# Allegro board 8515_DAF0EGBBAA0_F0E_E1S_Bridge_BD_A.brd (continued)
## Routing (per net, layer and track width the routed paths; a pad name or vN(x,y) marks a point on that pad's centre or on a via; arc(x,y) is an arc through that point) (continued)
P3E_E1S_2_RX_DN2: length 45.1
  TOP w0.132: v3(81.03,30.78) 81.4,30.4 81.68,30.4 82.45,31.17 82.89,31.17 83.02,31.3 J6.A23
  BOTTOM w0.132: GF1.A50 56.97,3.16 57.1,3.29 57.1,6.03 62.01,13.03 65.28,15.32 72.13,16.53 74.32,18.72 v4(75.42,24.94) 75.78,26.99 77.13,28.93 77.79,29.39 78.79,29.39 80.3,30.45 80.7,30.45 v3(81.03,30.78)
P3E_E1S_2_RX_DN3: length 45.4
  TOP w0.132: J6.A26 84.6,29.49 84.73,29.37 85.28,29.37 v3(85.62,29.7)
  BOTTOM w0.132: GF1.A53 58.77,3.16 58.84,3.23 58.84,5.76 58.92,6.18 62.9,11.86 66.28,14.23 69.39,14.78 v4(70.02,14.89) 70.44,14.97 72.7,15.37 74.5,16.6 75.46,17.56 75.65,17.83 75.86,18.13 76.57,19.32 76.63,19.71 77.15,22.63 77.16,22.64 77.78,26.11 78.41,27.02 80.03,28.15 81.25,28.15 82.78,29.22 83.96,29.43 84.33,29.37 85.28,29.37 v3(85.62,29.7)
P3E_E1S_2_RX_DP0: length 50.1
  TOP w0.132: v3(81.54,34.09) 81.87,34.42 82.89,34.42 83.02,34.3 J6.A18
  BOTTOM w0.132: GF1.A45 53.97,3.16 53.84,3.29 53.84,6.02 59.53,14.15 64.57,17.67 v4(65.33,17.8) 70.47,18.71 70.92,19.02 72.2,26.3 73.41,28.03 73.7,28.08 73.92,28.4 73.87,28.69 74.1,29.01 74.38,29.06 74.61,29.38 74.56,29.67 74.79,29.99 75.07,30.04 75.3,30.37 75.25,30.65 75.47,30.97 77.85,32.64 78.62,32.64 79.48,33.24 79.91,33.86 80.72,34.42 81.25,34.42 81.54,34.14 v3(81.54,34.09)
P3E_E1S_2_RX_DP1: length 51.1
  TOP w0.132: J6.A21 84.6,32.49 84.73,32.62 85.33,32.62 v3(85.67,32.29)
  BOTTOM w0.132: GF1.A48 55.77,3.16 55.64,3.29 55.64,5.94 60.81,13.32 65.13,16.35 71.21,17.42 72.45,18.28 73.17,22.35 73.41,22.52 73.48,22.91 73.31,23.15 73.38,23.54 73.62,23.71 73.69,24.1 73.52,24.34 73.59,24.73 73.83,24.89 73.9,25.28 73.73,25.52 73.8,25.91 74.78,27.31 74.86,27.42 76.73,30.1 v4(77.02,30.31) 77.36,30.54 77.72,30.8 78.63,30.8 80.66,32.22 81.04,32.28 81.81,32.28 82.39,32.54 83.44,32.77 84.23,32.61 85.46,32.61 85.67,32.39 v3(85.67,32.29)
P3E_E1S_2_RX_DP2: length 45.1
  TOP w0.132: v3(81.03,29.76) 81.33,30.06 81.83,30.06 82.59,30.82 82.89,30.82 83.02,30.7 J6.A24
  BOTTOM w0.132: GF1.A51 57.57,3.16 57.44,3.29 57.44,5.92 62.25,12.79 65.42,15 72.3,16.22 74.64,18.56 74.79,19.44 74.8,19.44 75,20.62 75.24,20.79 75.31,21.17 75.14,21.41 v4(75.22,21.87) 75.22,21.87 75.23,21.91 75.45,23.17 75.45,23.17 75.69,24.49 75.92,24.66 75.99,25.05 75.83,25.29 75.89,25.67 76.13,25.84 76.2,26.23 76.03,26.47 76.1,26.85 76.52,27.46 76.53,27.46 77.38,28.69 77.9,29.05 78.9,29.05 80.41,30.11 80.73,30.11 81.03,29.82 v3(81.03,29.76)
P3E_E1S_2_RX_DP3: length 45.4
  TOP w0.132: v3(85.62,28.69) 85.28,29.02 84.73,29.02 84.6,28.9 J6.A27
  BOTTOM w0.132: v3(85.62,28.69) 85.28,29.02 84.3,29.02 83.96,29.09 82.92,28.9 81.45,27.87 81.39,27.81 80.14,27.81 78.65,26.78 78.1,25.98 78.03,25.59 78.2,25.36 78.13,24.97 77.89,24.8 77.82,24.41 77.99,24.17 77.92,23.79 77.68,23.62 77.61,23.23 77.78,22.99 77.71,22.61 77.46,22.43 76.97,19.68 76.89,19.2 76.15,17.95 75.93,17.63 75.72,17.34 74.72,16.33 v4(74.01,15.85) 73.61,15.58 72.83,15.04 66.42,13.91 63.14,11.62 59.24,6.05 59.18,5.73 59.18,3.35 59.37,3.16 GF1.A54
P3E_E1S_2_TX_DN0: length 46.7
  TOP w0.132: GF1.B44 53.37,3.16 53.5,3.29 53.5,6.48 59.76,15.42 60.01,15.78 v4(60.34,16.25) 60.55,16.54 60.73,16.8 64.15,17.41 65.7,17.68 67.15,17.94 70.5,18.53 71.84,22.3 72.06,22.9 72.16,23.19 72.27,23.5 72.59,25.32 73.41,29.97 74.61,31.68 74.85,31.93 74.94,32.06 77.31,34.42 77.48,34.54 77.69,34.69 77.72,34.7 78.33,34.8 78.42,34.9 J6.B17
P3E_E1S_2_TX_DN1: length 45.5
  TOP w0.132: J6.B20 78.42,33.09 78.34,33.02 78.03,33.02 77.87,32.98 77.72,32.89 77.41,32.72 76.81,32.15 75.55,30.89 74.64,29.58 v4(74.64,28.54) 74.64,27.1 74.58,26.92 74.58,26.92 74.44,26.46 74.67,26.05 75.06,25.93 75.16,25.75 75.02,25.28 74.86,25.19 74.45,25.31 74.04,25.09 72.25,19.12 72.06,18.06 71.29,17.29 61.81,15.62 60.94,14.38 60.3,13.46 59.92,12.93 59.68,12.59 55.3,6.33 55.3,3.29 55.17,3.16 GF1.B47
P3E_E1S_2_TX_DN2: length 42.3
  TOP w0.132: GF1.B50 56.97,3.16 57.1,3.29 57.1,6.36 57.16,6.42 62.2,13.61 62.85,14.26 63.34,14.35 70.82,15.66 71.42,15.77 72.53,16.55 72.53,16.55 73.3,17.08 73.75,19.66 v4(74.43,21.89) 74.49,22.1 74.85,23.29 76.39,24.88 76.46,26.22 75.86,27.62 75.86,28.33 76.03,29.27 76.8,30.36 77.72,31.01 77.99,31.2 78.41,31.2 78.51,31.3 J6.B23
P3E_E1S_2_TX_DN3: length 41
  TOP w0.132: J6.B26 78.51,29.49 78.41,29.39 78.13,29.39 77.8,29.13 77.72,29.07 77.33,28.74 77.18,27.9 77.8,26.44 77.56,23.94 75.93,22.62 75.77,22.09 75.99,21.67 76.29,21.58 76.38,21.42 76.23,20.94 76.07,20.85 75.77,20.94 75.36,20.72 75.08,19.81 v4(74.95,19.13) 74.88,18.79 74.52,16.95 74.25,15.43 73.43,14.6 67,13.47 63.97,12.94 63.53,12.66 63.19,12.45 62.43,11.36 62.23,11.07 61.88,10.57 58.9,6.32 58.9,3.29 58.77,3.16 GF1.B53
P3E_E1S_2_TX_DP0: length 46.8
  TOP w0.132: J6.B18 78.5,34.3 78.33,34.46 77.83,34.37 77.72,34.3 77.53,34.16 75.21,31.84 75.11,31.71 74.87,31.47 73.73,29.84 73.48,28.42 73.65,28.18 73.58,27.79 73.34,27.63 73.27,27.24 73.44,27 73.37,26.61 73.13,26.45 73.07,26.06 73.23,25.82 73.16,25.43 72.93,25.27 72.6,23.41 72.16,22.19 70.75,18.23 66.52,17.48 65.59,17.32 62.94,16.85 62.81,16.83 60.93,16.49 60.46,15.82 60.28,15.57 60.04,15.22 57.59,11.73 v4(57.37,11.41) 57.1,11.03 53.84,6.38 53.84,3.29 53.97,3.16 GF1.B45
P3E_E1S_2_TX_DP1: length 45.5
  TOP w0.132: J6.B21 78.51,32.49 78.33,32.68 78.08,32.68 78,32.66 77.89,32.6 77.72,32.48 77.48,32.32 77.05,31.91 75.81,30.67 74.98,29.48 74.98,27.05 74.91,26.83 74.91,26.82 74.81,26.5 74.9,26.34 75.3,26.22 75.53,25.79 75.49,25.65 75.31,25.05 74.89,24.83 74.49,24.95 74.33,24.86 v4(72.67,19.33) 72.58,19.05 72.38,17.9 71.46,16.98 69.94,16.71 69.77,16.47 69.39,16.4 69.15,16.57 68.76,16.5 68.59,16.26 68.2,16.19 67.97,16.36 67.58,16.29 67.41,16.05 67.02,15.98 66.79,16.15 62,15.31 55.64,6.22 55.64,3.29 55.77,3.16 GF1.B48
P3E_E1S_2_TX_DP2: length 42.3
  TOP w0.132: GF1.B51 57.57,3.16 57.44,3.29 57.44,6.22 62.46,13.39 63.02,13.94 63.4,14.01 63.72,14.07 63.97,14.11 67.72,14.77 67.96,14.61 68.35,14.67 68.52,14.91 68.9,14.98 69.14,14.81 69.53,14.88 69.7,15.12 70.09,15.19 70.33,15.02 70.72,15.09 70.88,15.33 71.56,15.45 72.35,16.01 v4(72.84,16.35) 73.1,16.53 73.61,16.89 74.08,19.58 75.16,23.11 76.73,24.74 76.8,26.28 76.2,27.69 76.2,28.3 76.35,29.13 77.04,30.12 77.72,30.6 78.1,30.86 78.33,30.86 78.5,30.7 J6.B24
P3E_E1S_2_TX_DP3: length 41
  TOP w0.132: GF1.B54 59.37,3.16 59.24,3.29 59.24,6.21 63.43,12.2 64.09,12.61 64.54,12.69 v4(65.36,12.84) 65.78,12.91 66.6,13.05 69.88,13.63 70.12,13.47 70.51,13.53 70.67,13.77 71.06,13.84 71.3,13.67 71.69,13.74 71.86,13.98 72.24,14.05 72.48,13.88 72.87,13.95 73.04,14.19 73.6,14.29 74.57,15.26 74.86,16.88 75.41,19.73 75.64,20.48 75.81,20.57 76.1,20.48 76.52,20.7 76.75,21.46 76.52,21.87 76.23,21.96 76.14,22.12 76.23,22.42 77.88,23.76 78.15,26.49 77.53,27.94 77.64,28.55 77.72,28.62 78.02,28.87 78.24,29.05 78.37,29.05 78.52,28.9 J6.B27
P3E_E1S_3_RX_DN0: length 71.7
  TOP w0.132: J7.A17 108.52,34.9 108.39,34.77 107.37,34.77 v3(107.03,35.1)
  BOTTOM w0.132: v3(107.03,35.1) 106.72,34.79 103.15,34.79 100.81,33.15 100.65,32.25 99.96,28.33 99.67,26.72 v4(99.6,26.31) 99.54,26 97.86,16.46 94.64,14.2 90.25,13.42 83.98,14.53 80.05,13.83 76.86,14.39 75.61,14.39 68.11,13.07 67.97,13.05 66.83,12.85 64.57,11.26 63.72,10.42 60.89,6.46 60.69,5.31 60.69,3.28 60.57,3.16 GF1.A56
P3E_E1S_3_RX_DN1: length 71.7
  TOP w0.132: J7.A20 110.1,33.09 110.23,32.97 110.83,32.97 v3(111.17,33.3)
  BOTTOM w0.132: GF1.A59 62.37,3.16 62.5,3.29 62.5,5.4 62.71,6.59 65.07,9.95 65.5,10.32 67.39,11.64 70.86,12.25 v4(71.37,12.34) 71.4,12.35 71.75,12.41 75.4,13.05 76.83,13.05 78.94,12.68 78.94,12.68 79.34,12.61 79.83,12.53 83.48,13.17 89.76,12.06 95.4,13.06 99.2,15.72 100.89,25.1 101.78,30.06 102.45,30.74 103.07,31.12 103.31,31.17 103.72,31.17 104.17,31.24 104.8,31.8 105.22,32.16 105.73,32.48 106.1,32.58 107.31,32.58 107.67,32.81 107.75,32.84 108.18,32.97 110.83,32.97 v3(111.17,33.3)
P3E_E1S_3_RX_DN2: length 64.6
  TOP w0.132: J7.A23 108.52,31.3 108.34,31.11 107.9,31.11 107.18,30.4 106.9,30.4 v3(106.53,30.78)
  BOTTOM w0.132: v3(106.53,30.78) 106.15,30.4 105.77,30.4 105.34,29.98 104.35,27.95 103.01,26.61 101.14,15.97 100.2,14.64 98.26,13.28 96.33,11.93 89.81,10.78 85.86,11.47 v4(85.53,11.53) 85.16,11.6 83.52,11.88 79.44,11.16 76.17,11.74 76.04,11.76 75.82,11.76 75.77,11.76 75.77,11.75 75.68,11.74 75.62,11.73 75.53,11.71 75.48,11.7 67.9,10.37 65.51,7.98 64.6,6.68 64.34,5.2 64.3,4.98 64.3,3.29 64.17,3.16 GF1.A62
P3E_E1S_3_RX_DN3: length 65.2
  TOP w0.132: J7.A26 110.1,29.49 110.23,29.37 110.78,29.37 v3(111.12,29.7)
  BOTTOM w0.132: GF1.A65 65.97,3.16 66.1,3.29 66.1,5.62 66.33,6.92 68.42,9.01 75.39,10.25 76.42,10.25 78.02,9.97 78.1,9.96 78.11,9.96 79.18,9.77 83.63,10.55 90.61,9.32 97.12,10.47 100.75,13.01 101.77,14.48 102.8,15.95 103.35,19.07 v4(103.42,19.46) 103.49,19.83 104.66,26.51 106.17,28.02 106.29,28.09 109.47,29.36 109.8,29.39 110.34,29.39 110.8,29.39 v3(111.12,29.7)
P3E_E1S_3_RX_DP0: length 71.7
  TOP w0.132: J7.A18 108.52,34.3 108.39,34.42 107.37,34.42 v3(107.03,34.09)
  BOTTOM w0.132: v3(107.03,34.09) 106.67,34.45 103.26,34.45 101.12,32.95 100.85,31.43 101.01,31.19 100.95,30.8 100.71,30.63 100.64,30.24 100.81,30.01 100.74,29.62 100.5,29.45 100.43,29.06 100.6,28.83 100.53,28.44 100.29,28.27 98.17,16.26 94.77,13.88 90.25,13.08 83.98,14.18 80.05,13.49 76.83,14.05 75.64,14.05 68.17,12.74 v4(68.03,12.71) 68.03,12.71 66.96,12.52 64.79,11 63.98,10.19 61.21,6.33 61.03,5.28 61.03,3.3 61.17,3.16 GF1.A57
P3E_E1S_3_RX_DP1: length 71.6
  TOP w0.132: J7.A21 110.1,32.49 110.23,32.62 110.83,32.62 v3(111.17,32.29)
  BOTTOM w0.132: v3(111.17,32.29) 110.83,32.62 108.23,32.62 107.87,32.52 107.83,32.5 107.4,32.24 106.15,32.24 105.87,32.16 105.42,31.88 105.02,31.54 104.32,30.93 103.75,30.83 103.34,30.83 103.2,30.8 102.66,30.47 102.1,29.9 101.79,28.19 101.96,27.95 101.89,27.56 101.65,27.4 101.58,27.01 101.74,26.77 101.67,26.38 101.43,26.22 101.36,25.83 101.53,25.59 101.46,25.2 101.22,25.04 99.51,15.53 95.53,12.74 89.76,11.72 83.48,12.83 79.83,12.18 79.34,12.27 v4(78.88,12.35) 78.62,12.39 76.8,12.71 75.43,12.71 71.81,12.08 71.57,12.03 71.57,12.03 71.43,12.01 71.43,12.01 70.92,11.92 67.52,11.32 65.71,10.05 65.32,9.72 63.03,6.45 62.84,5.37 62.84,3.29 62.97,3.16 GF1.A60
P3E_E1S_3_RX_DP2: length 64.6
  TOP w0.132: J7.A24 108.52,30.7 108.44,30.77 108.04,30.77 107.33,30.06 106.83,30.06 v3(106.53,29.76)
  BOTTOM w0.132: v3(106.53,29.76) 106.22,30.06 105.91,30.06 105.62,29.78 104.63,27.75 103.33,26.44 103.22,25.84 103.39,25.6 103.32,25.21 103.08,25.05 103.01,24.66 103.18,24.42 103.11,24.03 102.87,23.87 102.8,23.48 102.97,23.24 102.9,22.85 102.67,22.68 102.6,22.3 102.76,22.06 102.7,21.67 102.46,21.5 101.46,15.84 101.12,15.35 100.45,14.39 96.46,11.6 89.81,10.43 86.67,10.98 83.52,11.54 81.48,11.18 79.44,10.82 77.78,11.11 76.01,11.42 75.85,11.42 75.74,11.4 75.61,11.38 75.57,11.37 v4(75.56,11.37) 75.54,11.37 75.45,11.35 75.03,11.28 75.03,11.28 68.06,10.05 68.01,9.99 65.77,7.76 64.93,6.55 64.69,5.2 64.64,4.95 64.64,3.29 64.77,3.16 GF1.A63
P3E_E1S_3_RX_DP3: length 65.2
  TOP w0.132: J7.A27 110.1,28.9 110.23,29.02 110.78,29.02 v3(111.12,28.69)
  BOTTOM w0.132: v3(111.12,28.69) 111.12,28.71 110.79,29.04 110.34,29.04 109.82,29.05 109.55,29.02 106.45,27.79 106.39,27.75 104.98,26.34 104.47,23.44 104.64,23.2 104.57,22.81 104.33,22.64 104.26,22.26 104.43,22.02 104.36,21.63 104.12,21.46 103.12,15.81 100.99,12.77 99.65,11.83 99.6,11.54 99.28,11.31 98.99,11.37 97.25,10.15 90.61,8.98 83.63,10.21 79.18,9.42 78.57,9.53 v4(78.04,9.62) 76.39,9.91 75.42,9.91 68.59,8.7 66.65,6.76 66.44,5.59 66.44,3.29 66.57,3.16 GF1.A66
P3E_E1S_3_TX_DN0: length 65.8
  TOP w0.132: GF1.B56 60.57,3.16 60.7,3.29 60.7,6.49 61.91,8.21 65,11.3 69.16,12.06 83.45,12.81 94.62,14.78 95.74,15.9 97.82,20.88 97.83,20.9 98.42,22.32 98.43,22.32 98.62,22.78 v4(98.57,23.26) 97.95,29.12 98.13,30.15 100.3,33.25 101.34,33.98 102.87,34.57 102.88,34.58 103.45,34.82 103.85,34.82 103.92,34.9 J7.B17
P3E_E1S_3_TX_DN1: length 64.6
  TOP w0.132: GF1.B59 62.37,3.16 62.5,3.29 62.5,6.3 63.62,7.9 65.59,9.86 66.28,10.18 67.67,10.51 77.31,11.03 77.31,11.03 77.42,11.03 77.45,11.03 78.77,11.11 80.27,11.24 82.76,11.4 97.51,14 99.22,17.37 99.22,17.39 99.23,17.38 100.72,20.31 100.62,20.82 v4(100.5,21.51) 100.36,22.33 99.3,28.37 99.22,29.2 100.04,30.38 101.11,31.91 101.44,32.38 102.87,32.82 102.99,32.85 103.82,33 103.92,33.09 J7.B20
P3E_E1S_3_TX_DN2: length 62.1
  TOP w0.132: J7.B23 103.89,31.3 103.84,31.25 103.33,31.25 102.87,31.01 102.29,30.71 100.88,28.68 101.13,27.25 101.13,27.24 101.54,24.89 102.28,20.65 102.28,19.51 v4(102.08,19.13) 101.92,18.81 99.34,13.79 99.12,13.39 98.62,12.85 98.46,12.77 81.58,9.79 80.02,9.74 v4(72.6,9.48) 71.73,9.45 69.16,9.36 66.62,8.91 64.3,6.65 64.3,3.29 64.17,3.16 GF1.B62
P3E_E1S_3_TX_DN3: length 61.6
  TOP w0.132: GF1.B65 65.97,3.16 66.1,3.29 66.1,6.14 66.82,7.17 68.07,7.81 70.13,8.09 81.67,8.35 82.01,8.35 99.47,11.43 99.64,11.66 101.89,14.75 v4(103.28,16.73) 104.04,17.81 104.3,18.19 104.36,18.5 104.05,20.25 104.32,20.63 105.05,20.76 105.15,20.91 105.06,21.41 104.91,21.52 104.18,21.39 103.8,21.66 103.35,24.18 103.35,24.18 103.15,25.34 103.14,25.36 103,26.15 102.71,27.8 102.7,27.89 102.7,27.89 102.67,28.04 102.85,29.06 103.04,29.23 103.24,29.39 103.77,29.39 103.87,29.49 J7.B26
P3E_E1S_3_TX_DP0: length 65.8
  TOP w0.132: GF1.B57 61.17,3.16 61.04,3.29 61.04,6.38 62.17,7.99 65.17,10.98 69.2,11.72 v4(74.56,12) 83.49,12.47 94.78,14.47 96.03,15.71 98.49,21.59 98.75,21.7 98.9,22.06 98.79,22.32 98.96,22.73 98.91,23.29 98.9,23.29 98.84,23.95 99.02,24.17 98.98,24.57 98.75,24.75 98.71,25.14 98.89,25.37 98.85,25.76 98.63,25.94 98.29,29.11 98.37,29.56 98.45,30.02 100.55,33.01 101.5,33.68 102.87,34.21 103.01,34.26 103.52,34.48 103.73,34.48 103.92,34.3 J7.B18
P3E_E1S_3_TX_DP1: length 64.6
  TOP w0.132: GF1.B60 62.97,3.16 62.84,3.29 62.84,6.19 63.88,7.68 65.78,9.58 66.39,9.86 67.72,10.17 77.33,10.69 77.34,10.69 77.45,10.69 77.47,10.69 v4(77.47,10.69) 77.48,10.69 78.8,10.77 80.3,10.9 82.8,11.06 82.8,11.06 97.74,13.69 99.53,17.23 101.07,20.25 100.96,20.88 100.69,22.39 99.85,27.2 100.01,27.44 99.95,27.83 99.71,27.99 99.63,28.41 99.57,29.11 100.24,30.07 100.53,30.12 100.75,30.44 100.7,30.73 100.93,31.05 101.22,31.1 101.44,31.43 101.39,31.71 101.65,32.09 103.07,32.52 103.88,32.66 104.05,32.49 J7.B21
P3E_E1S_3_TX_DP2: length 62.1
  TOP w0.132: GF1.B63 64.77,3.16 64.64,3.29 64.64,6.51 66.78,8.59 69.19,9.02 71.74,9.11 75.34,9.23 79.46,9.38 v4(80.04,9.4) 81.62,9.45 98.58,12.44 98.83,12.58 99.39,13.18 99.64,13.63 102.22,18.66 102.51,19.22 102.57,19.34 102.62,19.42 102.62,20.68 101.87,24.94 102.04,25.18 101.97,25.57 101.73,25.74 101.67,26.13 101.83,26.37 101.77,26.75 101.53,26.92 101.46,27.31 101.63,27.55 101.56,27.94 101.32,28.1 101.24,28.61 102.52,30.44 102.87,30.63 103.42,30.91 103.81,30.91 104.03,30.7 J7.B24
P3E_E1S_3_TX_DP3: length 61.6
  TOP w0.132: GF1.B66 66.57,3.16 66.44,3.29 66.44,6.04 67.05,6.9 68.17,7.48 70.16,7.75 81.67,8.01 82.04,8.01 99.67,11.12 99.73,11.2 v4(99.92,11.46) 102.17,14.55 104.62,18.05 104.7,18.5 104.41,20.17 104.51,20.32 105.24,20.45 105.51,20.84 105.37,21.61 104.99,21.88 104.26,21.75 104.11,21.86 103.69,24.24 103.85,24.48 103.79,24.86 103.55,25.03 103.48,25.42 103.65,25.66 103.58,26.04 103.34,26.21 103.27,26.6 103.44,26.84 103.37,27.23 103.13,27.39 103.06,27.81 103.02,28.04 103.16,28.88 103.36,29.05 103.77,29.05 103.92,28.9 J7.B27
PD_BIC_ADCREXT0: length 2.5
  TOP w0.109: R562.1 119.96,40.34 120.61,40.34 120.82,40.54 121.38,40.54 U35.F1
PD_BIC_ADCREXT1: length 3.8
  TOP w0.109: R564.1 119.27,39.4 119.38,39.29 121.54,39.29 121.95,39.7 U35.G2
PD_BIC_ENTEST: length 6.6
  TOP w0.109: R578.2 122.68,49.93 122.68,46.23 v4(122.17,45.72) 122.75,45.15 U35.A3
PD_FRU_E0: length 5.7
  TOP w0.109: v3(124.24,57.88) 124.84,57.28 125.22,57.28 125.63,57.68 U15.1
  BOTTOM w0.109: v3(124.24,57.88) 124.24,57.65 124.35,57.54 124.66,57.54 125.66,57.13 R275.2 R281.1
PECI_R: length 18.7
  TOP w0.109: U35.H14 v4(132.22,39.3)
  BOTTOM w0.109: R577.1 135.64,52.18 136.18,51.64 136.18,45.01 135.81,44.65 v1(135.81,43.74) 135.81,42.32 135.56,42.06 132.05,42.06 131.8,41.81 131.8,39.9 132.22,39.49 v4(132.22,39.3)
PRSNTA1_N: length 44.4
  TOP w0.109: R18.1 53.74,10.29 v3(53.56,10.11)
  IN1 w0.124: v3(53.56,10.11) 53.29,10.39 39.19,10.39 33.56,16.02 29.03,16.02 v3(28.86,15.86)
  BOTTOM w0.109: R18.1 53.74,10.29 v3(53.56,10.11) ; v3(28.86,15.86) 27.81,14.8 27.81,14.17 v1(27.39,13.75) 27.39,13.17 26.27,12.05 R16.2 26.52,11.68 R20.1 26.52,10.51 26.8,10.24 26.8,8.99 25.25,7.45 GF1.A10
PRSNTB0_N: length 12.1
  TOP w0.109: R18.2 52.53,10.31 51.66,10.31 v2(51.26,10.72) 50.33,10.07 48.02,7.76 47.86,7.08 GF1.B42
PRSNTB1_N: length 15.2
  BOTTOM w0.109: v1(55.17,10.34) 54.97,10.34 54.25,9.63 53.05,9.63 52.94,9.74 R19.1 51.37,9.14 50.93,9.14 50.06,8.99 48.52,8.26 47.86,7.6 GF1.A42
PRSNTB2_N: length 15.2
  BOTTOM w0.109: GF1.A12 26.45,8.01 27.12,8.68 27.97,8.68 29.72,10.43 29.72,12.27 29.16,12.83 v1(28.7,12.83) 27.96,12.83 R16.1
PRSNTB3_N: length 50.1
  TOP w0.109: v3(67.16,4.45) 67.23,4.37 68.28,4.37 68.97,3.67 GF1.B70
  IN2 w0.124: v3(27.81,9.32) 27.88,9.39 29.32,9.39 29.84,8.87 50.03,8.87 50.57,8.88 51.09,8.79 51.11,8.78 64.63,8.78 67.16,6.25 v3(67.16,4.45)
  BOTTOM w0.109: R20.2 v1(28.96,10.92) 28.96,10.33 27.95,9.32 v3(27.81,9.32)
PU_CLKREQ_0_N: length 2.7
  TOP w0.109: R215.1 34.74,37.72 33.97,38.49 v3(33.8,38.49) J4.A11
PU_CLKREQ_1_N: length 4.2
  TOP w0.109: J5.A11 60.06,38.49 60.4,38.15 R230.1 60.81,37.87 v2(61.72,36.96)
PU_CLKREQ_2_N: length 5.2
  TOP w0.109: J6.A11 84.44,38.49 85.01,37.92 86.51,37.92 v2(87.02,37.41) 87.68,36.75 R245.1
PU_CLKREQ_3_N: length 9.8
  TOP w0.109: v2(112.52,39.07) 112.81,38.78 112.81,35.85 112.15,35.18 111.68,35.18 R260.1 111.64,35.18 111.2,35.18 110.69,35.69 110.49,35.69 110.14,36.04 110.14,38.18 109.83,38.49 J7.A11
PU_DB800_HI_BW: length 119.9
  TOP w0.109: v3(118.86,14.58) 118.93,14.66 118.93,15.92 118.69,16.16 117.93,16.16 117.55,16.54 117.55,16.94 117.4,17.09 117.4,18.5 117.55,18.66 117.55,21.36 117.78,21.59 v3(117.78,22.2) ; U32.1 36.43,29.69 35.69,30.43 v3(35.69,31.15) R481.1
  IN2 w0.124: v3(35.69,31.15) 35.69,31.79 36.5,32.61 38.18,32.61 38.8,31.98 38.8,30.77 39.49,30.08 41.08,30.08 41.73,29.43 41.73,27.48 44.07,25.15 45.25,25.15 45.28,25.11 47.34,25.11 61.05,11.4 61.07,11.4 61.15,11.32 61.22,11.32 61.24,11.3 85.9,11.3 86.4,10.8 96.98,10.8 98.37,12.19 108.58,12.19 109.17,12.78 116.51,12.78 118.32,14.58 v3(118.86,14.58)
  BOTTOM w0.109: v3(117.78,22.2) 117.78,22.26 117.25,22.79 117.25,24.71 117.78,25.24 117.78,25.84 118.75,26.81 118.75,28.26 119.25,28.76 R723.1 ; R480.2 v1(36.97,31.91) 36.45,31.91 v3(35.69,31.15)
PU_DB800_HI_BW_R: length 4.9
  TOP w0.109: v4(122.57,31.88) 122.69,32.18 U35.T3
  BOTTOM w0.109: R723.2 119.25,30.32 119.77,30.84 v1(120.75,31.25) 120.96,31.46 122.23,31.46 122.57,31.8 v4(122.57,31.88)
PU_SMB_BMC_CPLD_SCL_G2: length 6
  BOTTOM w0.109: R427.1 132.7,20.35 132.7,21.64 v1(132.9,21.84) 133.14,21.6 134.51,21.6 134.85,21.94 135.14,22.64 135.36,22.86 Q1.5
PU_SMB_BMC_CPLD_SDA_G1: length 4.9
  BOTTOM w0.109: R426.1 132.33,20.13 132.33,22.66 v1(132.75,23.09) 133.26,23.09 133.49,22.86 Q1.2
PU_SMB_IPMB_AUX_SCL_G2: length 1.6
  TOP w0.109: Q2.5 115.31,16.16 v3(115.32,16.16) 115.32,15.72 R429.1
PU_SMB_IPMB_AUX_SDA_G1: length 3.1
  TOP w0.109: Q2.2 115.31,18.41 115.06,18.16 114.17,18.16 v3(113.65,18.68) 113.3,18.33 R428.1
PWRGD_EXP_PWROK: length 145.4
  TOP w0.109: GF1.OCP_B1 7.66,4.36 8.64,5.34 v3(8.64,7.62) ; v3(112.84,10.35) 112.83,10.36 112.83,11.97 112.43,12.38 112.1,12.51 110.78,13.84 110.78,14.07 110.36,14.49 110.36,16.58 110.24,16.7 110.24,18.2 110.35,18.31 111.48,18.31 111.86,18.7 111.86,19.58 111.37,20.07 111.37,20.63 110.85,21.16 110.85,23.26 111.2,23.62 111.2,26.06 113.82,28.68 113.82,32.62 113.74,32.69 113.74,33.59 114.39,34.23 117.41,34.23 118.11,33.53 118.31,33.53 118.47,33.37 R548.1
  IN1 w0.124: v3(8.64,7.62) 14.48,7.62 15.27,8.41 23.96,8.41 24.35,8.01 25.67,8.01 26.26,8.61 52.42,8.61 53.31,7.71 99.23,7.71 99.86,8.35 109.87,8.35 111.39,9.86 112.36,9.86 v3(112.84,10.35)
PWRGD_EXP_PWROK_R: length 4.7
  TOP w0.109: U35.L1 120.88,36.5 119.67,35.29 119.67,33.74 119.27,33.34 R548.2
PWRGD_P1V2_STBY_R: length 23.3
  TOP w0.109: U36.5 121.7,23.45 121.21,22.96 120.64,22.96 R90.2 120.54,22.37 120.4,22.23 119.1,22.23 119.1,22.23 118.47,22.86 C252.1 117.27,22.38 117.27,21.95 117.02,21.69 115.57,21.69 115.27,22 115.27,24.95 v3(114.95,25.27)
  BOTTOM w0.109: R794.2 118.47,32.92 118.08,32.53 116.86,32.53 116.23,31.9 116.23,31.21 116.42,31.02 116.42,30.61 116.23,30.41 116.23,30.39 115.91,30.07 115.91,26.13 115.78,25.8 115.25,25.27 v3(114.95,25.27)
PWRGD_P12V_AUX: length 175.4
  TOP w0.109: v3(116.38,28.66) 116.38,28.69 118.24,30.55 120.34,31.43 U35.T1
  IN1 w0.124: v3(116.38,28.66) 116.38,28.25 116.8,27.82 116.95,27.76 118.49,27.76 119.47,28.17 123.8,28.17 124.08,27.89 125.4,27.89 125.83,27.46 125.83,25.72 123.09,22.98 123.09,22.56 122.07,21.54 118.98,21.54 117.27,19.83 117.27,19.41 115.17,17.31 113.14,17.31 112.9,17.56 110.39,17.56 110.39,17.56 110.03,17.56 108.63,18.96 104.14,18.96 100.56,22.54 94.91,22.54 93.28,24.17 89.79,24.17 85.89,20.27 75.03,20.27 71.94,17.18 61.88,17.18 61.27,17.78 60.36,17.78 59.43,18.71 53.63,18.71 49.02,14.1 42.3,14.1 37.9,18.5 27.32,18.5 26.87,18.05 v3(26.47,18.05)
  IN2 w0.124: v3(26.47,18.05) 24.66,18.05 22.73,19.98 22.73,31.77 20.6,33.91 19.25,33.91 17.67,35.49 15.9,35.49 13.46,36.5 13.42,36.5 12.87,36.73 11.44,36.73 10.69,36.42 9.36,35.09 9.36,31.55 8.81,31 8.81,28.98 7.93,28.1 6.95,28.1 v3(6.6,28.45)
  BOTTOM w0.109: R514.2 v1(6.46,27.7) 6.6,27.85 v3(6.6,28.45)
RESET_R_EXTRST_N: length 4.4
  TOP w0.109: U43.1 119.76,12.21 119.13,11.58 v3(119.09,11.58) 118.83,11.33 116.49,11.33 116.22,11.06 R4596.2
RESET_R_N: length 12.7
  TOP w0.109: v3(115.14,11.43) 115.42,11.14 R4596.1 114.94,10.82 114.61,11.15 114.61,12.06 113.18,13.49 113.11,13.49 R4595.1
  BOTTOM w0.109: U46.4 114.61,11.96 v3(115.14,11.43) 115.98,10.59 v1(115.98,10.34) 117.81,10.34 118.53,11.06 118.53,12.13 118.9,12.5 R4612.2
RESET_R_SRST_N: length 1.9
  TOP w0.109: U42.2 114.62,12.78 R4595.2
RST_BIC_E1S_0_N: length 125.2
  TOP w0.109: v3(116.75,17.31) 117.01,17.58 117.01,20.76 v3(116.75,21.02) ; R539.2 v3(124.33,26.7) ; v3(29.36,38.87) 29.13,39.09 J4.B10
  IN2 w0.124: v3(116.75,17.31) 116.75,16.16 115.8,15.21 114.34,15.21 114.2,15.07 113.81,15.07 113.69,15.19 108.31,15.19 108.27,15.15 107.88,15.15 107.82,15.21 107.44,15.21 107.38,15.15 106.99,15.15 106.93,15.21 98.04,15.21 95.95,13.12 87.41,13.12 86.81,13.72 62.01,13.72 48.68,27.05 48.68,36.02 47.12,37.59 40.21,37.59 39.07,38.73 36.25,38.73 35.13,37.62 30.6,37.62 v3(29.36,38.87)
  BOTTOM w0.109: v3(116.75,21.02) 116.9,20.87 117.14,20.87 118.29,22.02 118.29,22.66 117.79,23.16 117.79,24.46 118,24.67 121.63,24.67 122.73,25.78 124.08,25.78 124.33,26.04 v3(124.33,26.7)
RST_BIC_E1S_0_R_N: length 7.9
  TOP w0.109: R539.1 124.61,28.09 124.84,28.32 124.84,29.61 R567.2 124.41,30.12 124.79,30.5 125.07,30.5 125.95,31.39 125.95,31.69 126.62,32.36 126.62,33.7 U35.P8
RST_BIC_E1S_1_N: length 87.4
  TOP w0.109: v3(52.71,39.25) 52.81,39.25 52.96,39.1 J5.B10 ; R540.2 v3(120.27,26.67)
  IN1 w0.124: v3(112.12,24.49) 112.98,24.49 113.17,24.68 116.83,24.68 117.74,25.59 119.01,25.59 120.1,26.67 v3(120.27,26.67)
  IN2 w0.124: v3(112.12,24.49) 109.43,21.79 98.32,21.79 95.52,24.6 87.49,24.6 84.81,21.92 84.73,21.92 84.64,21.83 60.83,21.83 58.24,24.42 58.24,26.18 56.49,27.94 54.58,27.94 53.21,29.31 53.21,38.84 52.81,39.25 v3(52.71,39.25)
RST_BIC_E1S_1_R_N: length 8
  TOP w0.109: R540.1 120.54,28.09 120.78,28.32 120.78,29.61 R569.2 120.42,30.27 123.25,31.44 124.34,31.66 124.62,31.93 U35.T5
RST_BIC_E1S_2_N: length 77.2
  TOP w0.109: v3(110.14,48.13) 112.52,48.13 114.51,46.13 114.66,46.13 114.66,46.13 115.34,46.13 116.16,45.31 v3(116.16,44.76) ; v3(85.37,47.78) 84.25,46.66 84.01,46.66 80.26,42.91 80.26,39.37 79.99,39.1 J6.B10 ; v3(120.92,26.67) 120.93,26.67 120.93,26.66 121.28,27.02 R541.2
  IN2 w0.124: v3(113.02,26.32) 113.15,26.45 116.8,26.45 117.54,27.18 120.78,27.18 120.93,27.03 120.93,26.67 v3(120.92,26.67) ; v3(85.37,47.78) 86.16,46.99 93.5,46.99 93.99,47.48 97.7,47.48 100.3,44.88 106.12,44.88 107.28,46.04 107.79,46.04 109.92,48.17 110.1,48.17 v3(110.14,48.13)
  BOTTOM w0.109: v3(116.16,44.76) 116.08,44.76 115.54,44.22 115.54,42.33 112.7,39.49 112.7,35.92 112.71,35.91 112.71,35.9 113.93,32.98 113.93,28.04 113.34,26.64 v3(113.02,26.32)
RST_BIC_E1S_2_R_N: length 8.5
  TOP w0.109: R541.1 121.69,28.09 121.79,28.19 121.79,29.61 R570.2 121.3,30.12 121.7,30.51 123.57,31.29 124.55,31.48 125.02,31.95 v4(125.02,32.9) U35.R6
RST_BIC_E1S_3_N: length 51.5
  TOP w0.109: R698.2 v3(122.3,26.67) ; v3(116.69,43.84) 116.37,43.84 115.69,44.52 115.69,45.24 115.22,45.71 114.39,45.71 113.1,47 109.87,47 108.38,45.52 107.96,45.52 105.66,43.22 105.66,39.55 105.21,39.1 J7.B10
  IN1 w0.124: v3(122.3,26.67) 121.82,27.15 119.32,27.15 119.07,27.05 118.27,26.24 117.22,26.24 117.02,26.44 115.96,26.44 115.86,26.34 113.91,26.34 113.1,25.53 v3(112.73,25.53)
  BOTTOM w0.109: v3(116.69,43.84) 116.59,43.94 116.36,43.94 116.25,43.83 116.25,42.49 113.09,39.33 113.09,36 114.31,33.05 114.31,27.36 v1(114.2,27.25) 113.74,26.14 113.13,25.53 v3(112.73,25.53)
RST_BIC_E1S_3_R_N: length 7.1
  TOP w0.109: U35.T6 125.31,32.4 125.31,31.84 124.56,31.08 123.65,31.08 122.67,30.67 R699.2 122.81,29.61 122.81,28.2 122.7,28.09 R698.1
RST_BIC_EXTRST_N: length 12.5
  TOP w0.109: R4603.2 R5.2 13.16,11.51 v2(12.42,10.77) 10.32,8.67 10.32,4.41 9.46,3.55 GF1.OCP_B4
RST_BIC_SRST_N: length 12
  TOP w0.109: GF1.OCP_B3 8.86,3.8 9.72,4.66 9.72,9.34 v2(11.15,10.77) 11.33,10.95 R792.2 R4602.2
RST_MB_N: length 132.5
  TOP w0.109: U35.M3 v4(122.62,35.3) ; R14.1 25.73,16.56 25.84,16.66 v3(26.48,16.66)
  IN1 w0.124: v3(26.48,16.66) 26.52,16.71 27.57,16.71 28.08,17.21 34.36,17.21 36.3,15.27 39.99,11.57 55.18,11.57 56,10.75 97.83,10.75 98.62,11.53 105.9,11.53 106.18,11.25 106.84,11.25 109.81,14.23 112.72,14.23 113.56,15.07 116.1,15.07 116.28,14.89 117.08,14.89 117.35,15.16 117.35,18.19 118.95,19.8 119.64,19.8 120.41,20.57 122.04,20.57 122.58,20.03 124.09,20.03 127.32,23.25 127.32,27.4 126.86,27.87 126.86,29.2 126.73,29.33 126.15,29.33 124.01,31.47 124.01,31.5 123.92,31.63 123.77,31.99 123.77,33.15 123.95,33.32 124.41,33.32 124.64,33.55 124.64,33.93 124.46,34.11 124,34.11 123.8,34.32 123.8,34.67 123.57,34.9 123.27,34.9 122.87,35.3 v4(122.62,35.3)
RST_MB_R_N: length 11.4
  TOP w0.109: R14.2 25.96,11.82 25.96,11.13 25.6,10.77 v2(24.89,10.77) 24.89,10.64 24.66,10.41 24.66,4.45 25.25,3.86 GF1.B10
RST_SMB_E1S_0_N: length 110.2
  TOP w0.109: J4.A9 33.97,39.69 v3(34.04,39.62)
  IN2 w0.124: v3(34.04,39.62) 34.29,39.88 37.29,39.88 38.07,40.67 39.72,40.67 40.59,39.8 40.59,38.73 40.79,38.53 47.39,38.53 49.54,36.38 49.54,27.74 56.79,20.49 82.17,20.49 88.67,13.98 95.46,13.98 101.99,20.51 111.67,20.51 112.22,19.96 113.1,19.96 113.79,20.65 113.79,22.25 114.54,23 v3(114.54,23.38)
  BOTTOM w0.109: v3(114.54,23.38) 114.54,24.11 114.99,24.56 116.51,24.56 117.22,25.27 R550.1
RST_SMB_E1S_0_R_N: length 13.5
  TOP w0.109: U35.M5 v4(124.22,35.3)
  BOTTOM w0.109: v4(124.22,35.3) 123.83,34.91 123.83,33.53 123.61,33.31 122.12,33.31 120.99,32.18 120.89,32.14 v1(120.57,32.27) 120.45,31.99 120.12,31.77 119.38,31.46 118.79,31.07 118.49,30.77 118.21,30.77 117.85,30.41 117.85,30.4 117.76,30.18 117.76,28.44 R574.2 118.21,27.94 117.24,27.94 R550.2
RST_SMB_E1S_1_N: length 78
  TOP w0.109: v3(57.1,39.06) 57.1,39.51 57.28,39.7 J5.A9 ; v3(116.89,30.43) 116.89,29.97 115.9,28.97 115.9,28.09 116.52,27.47 117.01,27.47 117.22,27.26 R695.1
  IN2 w0.124: v3(57.1,39.06) 57.1,38.51 61.47,34.14 61.47,33.83 62.63,32.67 63.44,31.86 63.44,31.65 65.61,29.48 67,29.48 69.61,26.87 75.65,26.87 78.47,24.05 83.72,24.05 87.45,27.78 90.59,27.78 90.88,27.49 94.32,27.49 97.36,30.53 99.69,30.53 101.7,32.54 105.79,32.54 105.96,32.37 108.77,32.37 108.99,32.16 108.99,31.37 109.76,30.6 115.2,30.6 115.44,30.36 116.82,30.36 v3(116.89,30.43)
RST_SMB_E1S_1_R_N: length 9.4
  TOP w0.109: R695.2 117.24,28.01 118.21,28.01 R575.2 118.24,28.05 118.75,28.56 118.75,29.28 119.94,30.47 122.42,31.5 122.71,31.5 122.96,31.75 123.1,32.07 123.42,32.39 123.42,32.9 U35.R4
RST_SMB_E1S_2_N: length 40
  TOP w0.109: J6.A9 84.53,39.7 v3(85.35,38.87) ; R561.1 116.42,32 116.31,32.11 116.31,32.32 115.85,32.79 v3(115.8,32.79)
  IN1 w0.124: v3(96.69,34.79) 96.91,34.79 98.48,36.35 100.36,36.35 101.9,37.9 104.57,37.9 106.09,36.39 106.47,36.77 108.4,36.77 109.42,35.76 112.61,35.76 115.57,32.79 v3(115.8,32.79)
  BOTTOM w0.109: v3(96.69,34.79) 96.14,34.24 95.25,34.24 94.27,35.22 92.33,35.22 91.71,35.84 v1(89.7,35.84) 87.2,35.84 85.35,37.68 v3(85.35,38.87)
RST_SMB_E1S_2_R_N: length 7.2
  TOP w0.109: R561.2 117.27,31.98 117.27,31.95 117.62,31.6 117.8,31.52 118.56,31.52 118.84,31.64 119.03,31.76 R576.2 120.11,32.35 120.52,32.76 120.68,33.14 120.68,34.32 120.86,34.5 121.82,34.5 U35.N2
RST_SMB_E1S_3_N: length 16.5
  TOP w0.109: R563.1 114.87,33.73 v3(115.59,33.73) ; v3(107.03,39.68) 107.03,39.49 107.29,39.22 108.27,39.22 108.75,39.7 J7.A9
  IN1 w0.124: v3(115.59,33.73) 112.94,36.39 112.23,36.39 111.43,36.39 110.99,36.82 109.49,36.82 108.88,37.44 108.88,38.98 108.69,39.17 107.5,39.17 107.03,39.65 v3(107.03,39.68)
RST_SMB_E1S_3_R_N: length 8.7
  TOP w0.109: U35.N1 120.51,34.9 120.31,34.7 v4(120.31,33.43) 120.31,33.11 120.01,32.82 119.34,32.54 116.97,32.54 116.49,33.02 R696.2 116.25,33.02 116.01,33.26 115.19,33.26 R563.2
SELECT_RST_N: length 4.2
  BOTTOM w0.109: U46.1 116.51,14.43 117.14,15.05 v1(117.58,15.05) 117.88,14.75 R4608.2 R4612.1
SELECT_RST_R_N: length 20.4
  TOP w0.109: v3(110.84,19.36) 110.59,19.6 110.59,20.27 109.83,21.03 108.94,21.03 108.64,21.34 108.28,21.34 108.07,21.12 U45.4
  BOTTOM w0.109: R4608.1 117.88,12.72 117.27,12.11 116.88,12.11 116.3,11.52 115.7,11.52 115.32,11.91 115.32,12.55 115.93,13.16 115.93,15.32 116.77,16.16 116.77,16.48 115.65,17.6 113.71,17.6 112.11,19.2 110.99,19.2 v3(110.84,19.36)
SGPIO_BMC_CLK_R: length 8
  TOP w0.109: R787.2 133.48,49.18 134.12,48.53 134.12,47.13 133.97,46.97 R783.1 133.6,46.32 132.43,45.15 131.94,45.15 131.43,44.64 v4(131.43,44.08) U35.B14
SGPIO_BMC_DOUT_R: length 9.6
  TOP w0.109: U35.D12 v4(130.62,42.5)
  BOTTOM w0.109: v4(130.62,42.5) 130.23,42.89 130.23,45.17 130.87,45.81 v1(130.93,45.81) 131.51,45.81 132.59,46.9 R774.1 132.08,47.48 132.08,48.6 132.53,49.05 R778.1
SLOT_ID0_R: length 12.1
  TOP w0.109: R8.2 15.9,11.46 15.21,10.77 v2(14.96,10.77) 14.96,9.93 12.19,7.16 12.19,4.83 11.26,3.89 GF1.OCP_B7
SLOT_ID1_R: length 10.5
  BOTTOM w0.109: R6.1 11.33,11.76 11.3,11.74 v1(11.3,11.05) 10.66,10.4 GF1.OCP_A6
SMB_BIC_E1S_0_R_SCL: length 7.2
  TOP w0.109: R211.2 137.52,30.99 136.3,30.99 135.79,30.48 R598.2 135.19,29.92 v3(134.49,29.92) 134.49,30.9 133.42,31.98 U35.T16
SMB_BIC_E1S_0_R_SDA: length 6.3
  TOP w0.109: R665.2 137.52,32 136.27,32 135.76,31.5 R599.2 134.31,31.5 133.81,32 v4(133.81,32.9) 133.81,32.9 U35.R16
SMB_BIC_E1S_1_R_SCL: length 6.9
  TOP w0.109: U35.P15 133.01,33.71 133.75,33.71 134.25,33.21 134.25,32.79 v4(134.68,32.36) 135.59,32.36 R600.2 136.25,33.02 137.52,33.02 R666.2
SMB_BIC_E1S_1_R_SDA: length 5.3
  TOP w0.109: R667.2 137.52,34.04 136.25,34.04 R602.2 135.17,34.1 v3(134.6,34.1) U35.P16
SMB_BIC_E1S_2_R_SCL: length 9.5
  TOP w0.109: v4(132.22,35.3) 131.42,35.3 U35.M13
  BOTTOM w0.109: v4(132.22,35.3) 132.86,35.94 v1(132.95,35.94) 132.95,35.39 133.53,34.81 134.96,34.81 135.22,34.55 135.22,34.05 R604.2 136.25,34.04 137.52,34.04 R709.2
SMB_BIC_E1S_2_R_SDA: length 6.8
  TOP w0.109: U35.N15 v4(133.01,34.5)
  BOTTOM w0.109: R710.2 137.52,33.02 136.29,33.02 135.78,32.51 R607.2 134.65,33.61 134.06,33.61 133.16,34.5 v4(133.01,34.5)
SMB_BIC_E1S_3_R_SCL: length 5.6
  TOP w0.109: v4(134.07,35.22) 133.75,34.9 U35.N16
  BOTTOM w0.109: R711.2 138.03,34.79 137.77,35.05 136.25,35.05 R713.2 135.07,35.22 v4(134.07,35.22)
SMB_BIC_E1S_3_R_SDA: length 8.2
  TOP w0.109: v4(134.72,35.67) 134.36,35.67 134.12,35.91 133.71,35.91 133.5,36.12 132.23,36.12 U35.M14
  BOTTOM w0.109: R712.2 138.03,35.71 137.03,36.72 v1(136.41,36.72) 136,36.72 135.74,36.46 R714.2 135.34,35.56 135.23,35.67 v4(134.72,35.67)
SMB_BIC_SENSOR_R_SCL: length 11.2
  TOP w0.109: U35.P13 v4(131.42,33.7)
  BOTTOM w0.109: R584.2 137.5,28.98 136.27,28.98 R611.2 135.58,28.45 134.67,29.36 134.21,29.36 133.81,29.76 133.81,30.92 133.18,31.55 132.41,31.55 131.42,32.54 v1(131.42,32.71) 131.42,32.71 v4(131.42,33.7)
SMB_BIC_SENSOR_R_SDA: length 10
  TOP w0.109: U35.N14 132.22,34.5 v4(132.22,33.7)
  BOTTOM w0.109: R586.2 137.52,29.97 136.25,29.97 R613.2 134.74,30.46 134.39,30.46 134.14,30.71 134.14,31.07 132.22,32.99 v4(132.22,33.7)
SMB_BMC_CPLD_SCL: length 134.3
  IN1 w0.124: v3(133.34,23.74) 134.77,22.3 134.77,20.92 135.3,20.39 135.3,16.48 134.42,15.6 134.42,10.84 133.14,9.56 131.63,8.93 117.93,8.93 116.05,10.81 116.05,11.32 115.71,11.66 115.71,11.66 115.43,11.93 115.43,11.94 115.04,12.33 113.66,12.33 113.54,12.21 111.87,12.21 109.59,9.94 107.8,9.94 107.51,9.64 105.51,9.64 105.23,9.92 99.49,9.92 98.61,9.03 53.98,9.03 53.05,9.96 39.02,9.96 33.62,15.36 27.71,15.36 27.29,14.94 26.42,14.94 v3(25.25,16.11)
  BOTTOM w0.109: v3(25.25,16.11) 24.85,16.51 v1(24.55,16.51) 24.05,16.51 23.21,15.67 R12.2 ; v3(133.34,23.74) 133.46,23.61 Q1.3
SMB_BMC_CPLD_SCL_R: length 13.6
  BOTTOM w0.109: GF1.A7 23.45,3.64 24.13,4.32 24.13,9.02 22.97,10.18 R21.2 22.97,12.47 v1(22.73,12.7) 23.21,13.17 R12.1
SMB_BMC_CPLD_SDA: length 129.5
  IN1 w0.124: v3(135.32,21.52) 135.73,21.11 135.73,16.31 134.92,15.5 134.92,10.73 133.37,9.18 131.55,8.43 115.45,8.43 113.05,10.82 111.71,10.82 109.66,8.78 99.68,8.78 99.05,8.14 53.52,8.14 52.62,9.04 38.6,9.04 34.42,13.22 26.82,13.22 26.7,13.35 v3(26.7,13.54)
  BOTTOM w0.109: v3(26.7,13.54) 25.78,13.54 25.4,13.92 v1(25.4,14.73) 24.87,15.26 R13.2 ; v3(135.32,21.52) 135.32,21.92 135.51,22.11 Q1.6
SMB_BMC_CPLD_SDA_R: length 14.7
  BOTTOM w0.109: GF1.A8 24.05,3.48 24.77,4.19 24.77,7.62 26.37,9.22 26.37,10.03 26.09,10.31 25.1,10.31 24.75,10.67 R22.2 24.75,12.47 v1(24.51,12.7) 24.22,12.99 R13.1
SMB_CLKBUF_SCL_R: length 145
  TOP w0.109: R494.2 v3(117.51,61.47) ; U32.9 37.62,25.17 37.48,25.03 36.68,25.03 35.97,24.33 35.97,21.53 39.6,17.9 39.6,16.15 v2(40.01,15.75) v3(40.01,14.22)
  IN1 w0.124: v3(40.01,14.22) 41.37,12.86 55.71,12.86 56.54,12.04 97.29,12.04 98.15,12.9 104.47,12.9 v3(107.19,15.62)
  BOTTOM w0.109: v3(107.19,15.62) 107.46,15.9 107.46,19.4 111.56,23.5 111.56,25.77 113.16,27.37 113.51,28.21 113.51,32.89 112.12,36.26 110.17,38.2 110.17,44.02 111.97,45.81 111.97,46.13 112.83,47 114.8,47 114.97,47.17 114.97,48.77 115.77,49.58 115.77,50.11 115.57,50.32 115.57,51.38 117.12,52.93 117.81,53.39 118.9,54.48 118.9,54.57 119.57,56.18 119.94,56.55 120.7,56.55 121.78,57.63 121.78,60.98 120.69,62.07 118.1,62.07 v3(117.51,61.47)
SMB_CLKBUF_SDA_R: length 2.9
  TOP w0.109: U32.10 38.12,25.04 37.61,24.53 v3(37.37,24.53) 37.08,24.53 36.58,24.02 R493.2
SMB_E1S_0_R_SCL: length 3.1
  TOP w0.109: v3(31.11,40.75) 31.26,40.89 J4.A7
  BOTTOM w0.109: v1(31.83,40.77) 31.75,40.77 31.75,40.77 31.13,40.77 v3(31.11,40.75) R418.1
SMB_E1S_0_R_SDA: length 4.3
  TOP w0.109: J4.A8 32.17,40.29 v3(31.62,39.75)
  BOTTOM w0.109: v3(31.62,39.75) 31.42,39.55 v1(30.66,39.55) 30.54,39.55 R419.1
SMB_E1S_0_SCL: length 184
  TOP w0.109: v3(139.71,28.35) 139.7,28.35 139.26,28.79 139.26,29.58 138.83,30.02 R211.1 ; R224.1 18.57,46.86 19.93,45.51 19.93,45.48 19.94,45.47 19.94,44.07 20.77,43.24 v2(21.05,43.24) v3(21.59,42.7)
  IN2 w0.124: v3(30.48,42.29) 30.12,42.65 29.24,42.65 28.02,41.43 28.02,29.54 27.33,28.85 27.33,15.95 27.73,15.55 27.73,14.19 27.33,13.79 27.33,11.13 28.19,10.27 31.13,10.27 31.24,10.16 49.56,10.16 50.3,10.9 56.47,10.9 57.3,10.06 85.39,10.06 85.89,9.56 97.49,9.56 98.15,10.22 108.44,10.22 109.4,11.18 113.05,11.18 113.34,10.88 115.97,10.88 116.64,10.21 126.44,10.21 127.47,11.24 127.47,12.79 129.9,15.23 130.37,15.23 131.07,15.93 131.07,16.21 131.93,17.07 131.93,21.8 132.88,22.75 134.01,22.75 135.19,23.93 135.94,23.93 136.37,24.36 136.37,25.08 136.92,25.63 138.46,25.63 139.06,25.03 139.8,25.03 140.28,25.51 140.28,26.65 140.83,27.2 140.83,28.73 140.52,29.05 139.85,29.05 139.71,28.91 v3(139.71,28.35)
  BOTTOM w0.109: R418.2 v3(30.48,42.29) 30.07,42.7 v3(21.59,42.7)
SMB_E1S_0_SDA: length 183
  TOP w0.109: R225.1 15.24,47.37 16.28,46.94 16.68,46.54 17.06,46.38 18.47,46.38 19.51,45.34 19.51,44.58 19.52,44.56 19.52,43.78 v2(19.18,43.43) 20.7,41.91 v3(21.08,41.91) ; v3(140.34,28.5) 140.34,29.99 140.27,30.05 140.27,31.13 139.91,31.5 R665.1
  IN2 w0.124: v3(29.59,42.16) 29.44,42.16 28.45,41.17 28.45,29.21 27.76,28.52 27.76,16.13 28.16,15.73 28.16,13.93 27.76,13.54 27.76,11.43 28.49,10.7 31.31,10.7 31.42,10.59 49.39,10.59 50.12,11.33 56.64,11.33 57.48,10.49 85.56,10.49 86.07,9.99 97.31,9.99 98,10.68 108.29,10.68 109.88,12.27 115.01,12.27 115.92,11.36 117.1,11.36 117.74,10.72 119.4,10.72 120.15,11.47 121.7,11.47 122.71,12.47 126.53,12.47 130.1,16.04 130.1,16.52 130.41,16.84 130.56,16.84 131.49,17.77 131.49,18.56 131.44,18.62 131.44,18.89 130.86,19.47 130.86,19.86 131.44,20.44 131.44,21.96 132.66,23.18 133.83,23.18 135.08,24.43 135.8,24.43 135.93,24.56 135.93,25.36 136.67,26.11 138.26,26.11 138.85,26.7 138.85,27.62 139.08,27.85 140.02,27.85 140.34,28.17 v3(140.34,28.5)
  BOTTOM w0.109: v3(21.08,41.91) 21.4,42.23 29.52,42.23 v3(29.59,42.16) 29.34,41.91 R419.2
SMB_E1S_1_R_SCL: length 4
  TOP w0.109: v3(56.58,41.65) 56.58,41.48 57.17,40.9 J5.A7
  BOTTOM w0.109: v1(56.58,42.88) v3(56.58,41.65) 56.58,41.66 R420.1
SMB_E1S_1_R_SDA: length 3.6
  TOP w0.109: v3(56.64,40.64) 56.77,40.64 57.11,40.3 J5.A8
  BOTTOM w0.109: R421.1 56.15,40.64 v3(56.64,40.64) 56.68,40.6 v1(57.59,40.6)
SMB_E1S_1_SCL: length 173.4
  TOP w0.109: v3(139.49,32.51) R666.1 ; v3(40.43,44.26) 40.89,44.73 R239.1
  IN2 w0.124: v3(105.59,17.27) 105.71,17.14 108.28,17.14 108.56,17.43 115.13,17.43 119.08,21.38 121.94,21.38 122.73,20.59 125.07,20.59 129.94,25.45 129.94,26.1 130.23,26.39 130.71,26.39 131.42,25.68 133.96,25.68 136.24,27.96 137.27,27.96 137.78,28.47 137.78,30.8 v3(139.49,32.51)
  BOTTOM w0.109: v3(105.59,17.27) 105.59,18.8 110.72,23.93 110.72,26.1 112.46,27.84 112.68,28.38 112.68,32.67 112.66,32.77 111.93,34.54 110.78,35.69 109.26,35.69 108.57,36.37 108.56,36.37 108.19,36.74 105.86,36.74 104.43,38.17 103.2,38.17 103.13,38.1 100.89,38.1 98.89,36.1 95.04,36.1 91.77,39.37 91.77,45.34 90.85,46.26 81.98,46.26 74.47,38.76 74.02,38.76 73.59,39.19 73.59,41.8 72.72,42.67 72.72,48.87 70.89,50.7 67.18,50.7 65.5,49.01 64.47,46.52 64.47,41.65 62.88,40.06 59.76,40.06 58.67,41.15 55.61,41.15 R420.2 54.43,41.66 v1(52.6,43.48) 52.4,43.48 50.66,45.23 49.26,45.23 47.24,47.24 43.92,47.24 43.64,47.52 42.06,47.52 40.43,45.89 v3(40.43,44.26)
SMB_E1S_1_SDA: length 172.5
  TOP w0.109: v3(139.5,33.2) 139.17,33.53 R667.1 ; v3(39.73,44.3) 39.88,44.45 R240.1
  IN2 w0.124: v3(139.5,33.2) 139.12,33.2 137.92,32 136.96,32 136.63,31.67 136.63,28.95 134.46,26.79 134.12,26.79 133.76,27.15 129.08,27.15 128.91,26.97 128.91,26.42 125.53,23.04 125.53,22.48 125.12,22.07 123.45,22.07 123.22,22.3 121.88,22.3 121.42,21.84 118.86,21.84 114.88,17.86 109.86,17.86 109.28,18.44 105.63,18.44 104.95,17.76 v3(104.95,17.27)
  BOTTOM w0.109: v3(104.95,17.27) 104.95,17.83 105.17,18.06 105.17,19.02 108.28,22.13 108.28,23.4 110.3,25.43 110.3,26.27 112.11,28.08 112.27,28.46 112.27,32.62 112.26,32.65 111.62,34.2 110.77,35.05 109.31,35.05 108.4,35.96 108.39,35.96 108.02,36.33 105.69,36.33 104.26,37.76 103.47,37.76 103.38,37.67 101.04,37.67 99.06,35.69 94.87,35.69 91.24,39.32 91.24,41.25 91.13,41.36 90.26,41.36 90.15,41.47 90.15,41.87 90.26,41.98 91.13,41.98 91.24,42.09 91.24,42.49 91.13,42.6 90.26,42.6 90.15,42.71 90.15,43.11 90.26,43.22 91.13,43.22 91.24,43.32 91.24,45.15 90.8,45.59 90.09,45.59 89.98,45.48 89.98,44.43 89.87,44.32 89.48,44.32 89.37,44.43 89.37,45.48 89,45.85 82.22,45.85 81.67,45.3 81.67,45.15 82.24,44.58 82.24,44.42 81.96,44.14 81.81,44.14 81.24,44.71 81.08,44.71 72.32,35.95 71.3,35.95 69.27,35.55 69.23,35.53 68.85,35.37 68.73,35.32 65.95,35.32 65.12,36.15 65.12,36.31 65.44,36.62 65.44,36.78 65.15,37.06 65,37.06 64.68,36.74 64.53,36.74 64.25,37.03 64.25,37.18 64.56,37.49 64.56,37.65 64.28,37.93 64.13,37.93 63.81,37.62 63.66,37.62 63.37,37.9 63.37,38.05 63.69,38.37 63.69,38.52 63.41,38.8 63.25,38.8 62.94,38.49 62.78,38.49 61.62,39.65 59.41,39.65 59,40.06 56.49,40.06 56.31,39.88 55.61,39.88 R421.2 54.41,40.39 v1(52.91,41.88) 52.89,41.93 50.08,44.74 49.16,44.74 47.09,46.81 43.89,46.81 43.51,46.43 42.93,46.43 42.82,46.32 42.82,45.65 42.71,45.54 42.31,45.54 42.2,45.65 42.2,46.32 42.1,46.43 41.68,46.43 41.05,45.8 41.05,44.22 40.61,43.79 40.06,43.79 39.71,44.13 39.71,44.29 v3(39.73,44.3)
SMB_E1S_2_R_SCL: length 3.2
  TOP w0.109: v3(82.26,40.39) 82.3,40.39 82.81,40.9 J6.A7
  BOTTOM w0.109: v1(82.93,40.82) 82.93,40.74 82.58,40.39 v3(82.26,40.39) R422.1
SMB_E1S_2_R_SDA: length 4.3
  TOP w0.109: v3(82.17,39.62) 82.42,39.62 83.09,40.3 J6.A8
  BOTTOM w0.109: v1(83.44,38.99) 82.8,39.62 v3(82.17,39.62) 81.68,39.14 R423.1
SMB_E1S_2_SCL: length 128.2
  TOP w0.109: v3(70.1,29.72) 69.98,29.59 69.98,28.74 69.87,28.63 68.5,28.63 68.45,28.68 68.15,28.68 68.07,28.75 R254.1
  IN2 w0.124: v3(70.1,29.72) 70.64,30.25 74.19,30.25 76.83,32.89 78.11,32.89 79.63,34.42 79.63,37.97 v3(81.28,39.62) 81.79,39.12 82.45,39.12 83.13,39.8 84.1,39.8 84.35,40.06 84.35,44.07 85.6,45.31 93.53,45.31 96.42,42.42 101.18,42.42 101.7,42.94 108.79,42.94 108.91,43.07 108.91,44.05 110.66,45.8 110.66,46.35 110.66,46.7 111.71,47.75 112.99,48.28 115.4,50.69 115.4,51.87 119.05,55.52 119.05,56.16 119.41,56.52 123.01,56.52 123.7,57.21 123.7,59.08 124.14,59.51 126.52,59.51 126.67,59.66 128.04,59.66 128.32,59.94 129.76,59.94 130.28,59.42 130.28,58.84 130.83,58.29 132.01,58.29 133.01,59.29 139.25,59.29 v3(139.87,58.67)
  BOTTOM w0.109: R709.1 138.83,33.83 139.01,34.01 139.54,34.01 139.81,34.28 139.81,38.33 139.03,39.1 139.03,40.21 138.45,40.8 138.45,41.88 138.13,42.2 138.13,43.61 138.64,44.12 138.64,52.55 138.4,52.78 138.4,53.09 138.54,53.23 138.54,53.33 139.27,54.06 139.27,55.64 139.27,55.64 139.27,58.07 v3(139.87,58.67) ; v1(81.41,42.16) 80.88,41.64 R422.2 81.03,40.24 81.03,39.88 v3(81.28,39.62)
SMB_E1S_2_SDA: length 125.2
  TOP w0.109: v5(70.87,29.72) 70.52,29.37 70.52,28.53 70.18,28.19 67.44,28.19 67.32,28.32 66,28.32 65.88,28.43 R255.1
  IN2 w0.124: v5(70.87,29.72) 74.27,29.72 77.01,32.46 78.28,32.46 80.06,34.24 80.06,37.77 80.39,38.1 v3(81.15,38.1) 81.66,38.61 82.55,38.61 83.31,39.37 87.25,39.37 91.92,44.04 94.03,44.04 96.09,41.99 101.43,41.99 101.94,42.5 109.23,42.5 109.35,42.62 109.35,43.88 111.09,45.62 111.09,46.52 111.95,47.38 113.23,47.92 115.17,49.85 115.89,49.85 117.39,51.35 117.39,53.26 119.48,55.35 119.48,55.83 119.73,56.09 123.22,56.09 124.6,57.46 125.53,57.46 126.49,58.42 128.45,58.42 128.8,58.06 129.85,58.06 130.94,56.97 131.34,56.97 132.75,58.38 139.28,58.38 v3(139.85,57.82)
  BOTTOM w0.109: v3(139.85,57.82) 140.41,57.25 140.41,54.35 138.92,52.85 139.05,52.72 139.05,43.94 138.55,43.44 138.55,42.37 138.86,42.06 138.86,40.97 139.45,40.38 139.45,39.3 140.36,38.39 140.36,32.71 139.68,32.04 139.3,32.04 R710.1 ; v3(81.15,38.1) 80.77,38.48 80.77,38.88 R423.2
SMB_E1S_3_R_SCL: length 5.2
  TOP w0.109: v3(108.1,41.96) 108.1,41.38 108.58,40.9 J7.A7
  BOTTOM w0.109: v3(108.1,41.96) 108.1,42.24 v1(107.7,42.65) 105.84,42.65 R424.1
SMB_E1S_3_R_SDA: length 5.7
  TOP w0.109: v3(107.21,42.01) 107.21,41.63 108.55,40.3 J7.A8
  BOTTOM w0.109: v3(107.21,42.01) 107.21,41.35 v1(106.69,40.83) 106.63,40.77 R425.1
SMB_E1S_3_SCL: length 83.8
  TOP w0.109: v5(98.42,37.59) 98.42,37.41 97.08,36.06 96.14,36.06 95.65,36.56 R269.1
  IN1 w0.124: v3(107.63,43.45) 107.63,43.25 107.95,42.93 108.48,42.93 111.21,45.65 111.21,47.18 113.4,49.36 113.4,51.85 116.92,55.38 117.39,56.5 117.39,57.91 117.4,57.92 117.4,58.04 119.46,60.1 120.85,60.1 120.97,60.21 123.92,60.21 124.06,60.07 128.35,60.07 128.35,60.08 130.04,60.08 130.36,60.4 v3(131.2,60.4)
  BOTTOM w0.109: v3(107.63,43.45) 107.29,43.1 104.93,43.1 104.68,42.86 R424.2 104.27,41.88 99.07,41.88 98.23,41.05 98.23,37.79 v5(98.42,37.59) ; v3(131.2,60.4) 131.53,60.4 133.84,58.1 133.84,57.57 134.92,56.49 135.62,56.49 138.13,53.97 138.13,53.4 137.99,53.26 137.99,52.61 138.23,52.37 138.23,44.29 137.72,43.78 137.72,42.03 138.03,41.71 138.03,41 138.04,41 138.04,40.57 138.62,39.99 138.62,38.9 139.31,38.21 139.31,34.73 139.13,34.54 R711.1
SMB_E1S_3_SDA: length 83.6
  TOP w0.109: v3(99.14,38.33) 99.25,38.21 99.25,37.53 98.68,36.96 98.55,36.96 97.25,35.65 95.81,35.65 R270.1
  IN1 w0.124: v3(106.55,41.99) 106.55,42.29 106.76,42.5 108.7,42.5 111.64,45.44 111.64,47 113.78,49.14 113.83,49.18 113.83,51.67 117.31,55.15 117.83,56.41 117.83,57.87 119.63,59.67 121.03,59.67 121.14,59.78 123.74,59.78 123.88,59.64 128.21,59.64 128.5,59.36 128.5,58.29 128.75,58.04 130.35,58.04 130.61,58.29 130.61,59.38 130.99,59.76 v3(131.2,59.76)
  BOTTOM w0.109: R712.1 138.83,38.09 138.19,38.73 138.19,39.77 137.62,40.34 137.62,40.83 137.62,40.83 137.62,41.54 137.3,41.86 137.3,43.95 137.81,44.46 137.81,52.2 137.15,52.86 137.15,53.87 135.78,55.25 135.06,55.25 132.77,57.54 132.77,58.19 v3(131.2,59.76) ; v3(99.14,38.33) 99.14,38.66 98.65,39.14 98.65,40.79 99.32,41.45 103.99,41.45 R425.2 104.68,40.77 105.56,41.66 106.22,41.66 v3(106.55,41.99)
SMB_FRU_SCL_R: length 3
  TOP w0.109: R277.2 120.59,60.45 120.82,60.22 U15.6 122.12,60.22 v3(122.61,60.71)
SMB_FRU_SDA_R: length 3.2
  TOP w0.109: U15.5 120.07,61.49 v2(119.81,61.75) 119.15,62.41 R278.2
SMB_INA230_E1S_0_SCL: length 4.6
  TOP w0.109: U11.5 13.98,48.5 14.22,48.26 14.99,48.26 15.27,47.97 15.79,47.97 v2(16.1,47.67) 16.27,47.5 16.45,47.5 17.08,46.86 R224.2
SMB_INA230_E1S_0_SDA: length 2.7
  TOP w0.109: R225.2 13.26,47.94 v3(13.26,49.07) U11.4
SMB_INA230_E1S_1_SCL: length 3.2
  TOP w0.109: U12.5 40.12,46.62 R239.2 42.22,45.92 v2(42.29,45.85)
SMB_INA230_E1S_1_SDA: length 3.9
  TOP w0.109: U12.4 39.39,46.22 R240.2 39.73,45.85 39.32,45.85 v2(38.53,45.06)
SMB_INA230_E1S_2_SCL: length 2
  TOP w0.109: R254.2 66.33,29.29 65.92,29.29 65.77,29.43 U13.5
SMB_INA230_E1S_2_SDA: length 2.5
  TOP w0.109: U13.4 65.05,29.85 v3(64.48,29.28) 65.01,28.75 R255.2
SMB_INA230_E1S_3_SCL: length 2.7
  TOP w0.109: U14.5 93.46,36.97 v2(93.65,36.78) 93.7,36.83 R269.2
SMB_INA230_E1S_3_SDA: length 4.8
  TOP w0.109: U14.4 92.73,36.58 93.49,35.82 v3(93.81,35.82) 94.84,35.82 R270.2
SMB_IO_EXP_SCL: length 14.3
  TOP w0.109: U48.22 v3(143.84,26.31)
  BOTTOM w0.109: R796.1 136.09,27.28 136.34,27.53 138.83,27.53 v1(139.07,27.29) 139.07,27.05 139.71,26.41 139.71,25.21 140.27,24.65 140.93,24.65 141.5,25.22 ; 141.5,25.22 141.96,24.77 143,24.77 143.36,25.13 143.36,25.92 143.75,26.31 v3(143.84,26.31) ; 141.5,25.22 U44.8
SMB_IO_EXP_SDA: length 19
  TOP w0.109: U48.23 v3(143.87,26.96)
  BOTTOM w0.109: R795.1 135.18,26.97 136.17,27.96 139.08,27.96 139.24,28.13 139.24,28.55 139.53,28.83 139.98,28.83 140.11,28.96 140.66,28.96 140.88,29.19 140.9,29.19 141.69,29.98 142.59,29.98 v1(142.61,29.97) 142.84,29.74 142.84,29.15 143,28.99 143,27.71 142.67,27.38 142.39,27.38 142,26.99 U44.9 142,25.41 142.21,25.2 142.72,25.2 142.94,25.41 142.94,26.12 143.77,26.96 v3(143.87,26.96)
SMB_IPMB_3V3AUX_SCL: length 2.1
  TOP w0.109: R433.1 137.52,35.05 136.78,35.05 136.54,34.82 R680.2
SMB_IPMB_3V3AUX_SDA: length 2.1
  TOP w0.109: R681.2 136.54,35.96 136.65,36.07 137.52,36.07 R402.1
SMB_IPMB_3V3SB_SCL: length 116.8
  TOP w0.109: R1.1 v3(17.73,13.61) ; Q2.3 114.56,19.28 114.41,19.43 112.61,19.43 111.79,20.26 111.79,21.59 v3(111.48,21.9)
  IN1 w0.124: v3(111.48,21.9) 111.13,21.9 110.69,22.33 105.45,22.33 98.93,28.85 91.98,28.85 91.59,28.47 90.08,28.47 84.68,23.07 73.59,23.07 71.84,21.32 65.34,21.32 65.15,21.13 63.73,21.13 62.46,22.4 53.17,22.4 48.9,26.67 45.09,26.67 42.21,23.79 33.9,23.79 32.82,22.71 26.04,22.71 21.79,18.47 21.79,14.5 19.89,12.6 18.75,12.6 v3(17.73,13.61)
SMB_IPMB_3V3SB_SCL_R: length 12.3
  TOP w0.109: R1.2 R23.2 16.81,11.35 v2(16.23,10.77) 16.23,10.39 13.66,7.82 GF1.OCP_B11
SMB_IPMB_3V3SB_SDA: length 120.5
  TOP w0.109: R9.1 v3(18.64,13.61) ; Q2.6 116.06,17.38 116.55,17.87 116.55,19.19 116.29,19.45 115.02,19.45 114.59,19.88 112.77,19.88 112.29,20.36 112.29,21.94 v3(111.58,22.65)
  IN1 w0.124: v3(111.58,22.65) 110.98,22.65 110.1,23.53 104.86,23.53 99.09,29.3 92.29,29.3 92.1,29.49 90.5,29.49 84.5,23.5 73.41,23.5 71.66,21.75 65.16,21.75 64.97,21.56 63.91,21.56 62.42,23.05 61.84,23.05 61.32,23.56 52.61,23.56 49.08,27.1 43.54,27.1 42.29,25.86 41.45,25.86 40.26,24.66 39.42,24.66 38.96,25.12 36.73,25.12 35.87,24.26 33.69,24.26 32.62,23.19 32.61,23.19 32.61,23.19 25.91,23.19 21.36,18.64 21.36,14.71 19.74,13.08 19.18,13.08 v3(18.64,13.61)
SMB_IPMB_3V3SB_SDA_R: length 12.8
  TOP w0.109: R24.2 R9.2 18.64,11.91 v2(17.5,10.77) 14.26,7.53 GF1.OCP_B12
SMB_IPMB_AUX_SCL_R: length 67.1
  TOP w0.109: R433.2 138.83,34.25 139.04,34.04 139.77,34.04 141.45,32.36 142.35,32.36 143.56,31.15 143.56,30.01 143.45,29.9 141.52,29.9 140.94,29.32 140.94,28.04 140.78,27.88 139.42,27.88 139.16,28.14 139.16,28.14 137.96,29.35 137.96,29.68 137.67,29.97 136.4,29.97 135.22,28.8 135.22,26.13 134.43,25.34 134.43,20.97 135.22,20.19 135.22,20.08 135.22,20.08 135.22,16.91 135.22,16.9 135.22,16.85 135.19,16.82 134.04,14.05 129.08,9.09 116.08,9.09 115.85,9.33 114.2,10.01 113.78,10.43 113.78,11.41 v3(113.72,11.46) 113.72,12.34 112.99,13.07 112.64,13.21 111.61,14.25 111.61,14.77 112.02,15.19 113.14,15.19 113.3,15.35 R413.2 113.3,16.22 113.55,16.46 114.15,16.46 114.56,16.87 Q2.4
SMB_IPMB_AUX_SDA_R: length 72.1
  TOP w0.109: R402.2 138.83,35.24 139.01,35.05 139.37,35.05 141.54,32.89 142.42,32.89 144.05,31.26 144.05,29.22 143.61,28.78 142.39,28.78 141.07,27.46 139.21,27.46 137.67,29 136.01,29 135.64,28.63 135.64,25.81 134.85,25.02 134.85,21.14 135.63,20.36 135.63,20.25 135.64,20.25 135.64,20.18 135.65,20.17 135.65,16.8 135.64,16.77 135.64,16.74 135.61,16.71 134.29,13.51 129.44,8.66 115.92,8.66 115.62,8.97 113.93,9.67 113.34,10.25 113.34,10.73 113.25,10.82 113.25,12.18 112.7,12.73 112.64,12.75 112.61,12.78 112.58,12.79 112.54,12.79 112.35,12.87 111.19,14.03 111.19,14.25 110.77,14.66 110.77,15.42 v5(111.11,15.76) 111.66,16.31 112.68,16.31 R412.1 113.26,17.07 113.84,17.65 115.44,17.65 116.06,18.27 Q2.1
